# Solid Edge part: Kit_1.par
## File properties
Sűrűség: 0,000 kg/m^3
Pontosság: 0,990
Author: ahadarics
Last saved by: ahadarics
Revision: 79
Username: ahadarics
Dokumentum tartalom típus: 0
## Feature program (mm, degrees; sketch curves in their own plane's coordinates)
base feature "unnamed BaseFeature 1"
thread "unnamed Thread 1"
sketch for "unnamed Hole 1" plane through (0, 0, 93.7) normal (0, 0, 1) x-axis (0, -1, 0)
  hole centre (-16.25, 16.25) bore radius 2.4585
hole "unnamed Hole 1" through
sketch for "unnamed Hole 2" plane through (0, 0, 93.7) normal (0, 0, 1) x-axis (0, -1, 0)
  hole centre (16.25, 16.25) bore radius 2.4585
hole "unnamed Hole 2" through
sketch for "unnamed Hole 3" plane through (0, 0, 93.7) normal (0, 0, 1) x-axis (0, -1, 0)
  hole centre (16.25, -16.25) bore radius 2.4585
hole "unnamed Hole 3" through
sketch for "unnamed Hole 4" plane through (0, 0, 93.7) normal (0, 0, 1) x-axis (0, -1, 0)
  hole centre (-16.25, -16.25) bore radius 2.4585
hole "unnamed Hole 4" through
pattern "unnamed Pattern 1" of "unnamed Hole 1", "unnamed Hole 2", "unnamed Hole 3", "unnamed Hole 4"
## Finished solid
Body 1: solid body, 318 faces, 747 edges, 450 vertices, 4 internal voids.
  Faces by surface: plane 145, cylinder 71, swept 55, torus 25, cone 21, spline 1
  Edges by curve: line 433, circle 187, spline 122, curve on surface 4, intersection 1
Bounding box of the edges (mm; curved faces can reach further): 49.000 x 49.000 x 14.100, from (-24.5, -24.5, 79.6) to (24.5, 24.5, 93.7).
Cylindrical faces by radius (mm): R0.2 x30, R0.335 x1, R0.5307 x1, R1.25 x1, R2.4585 x4, R2.5402 x12, R2.6 x4, R3.75 x4, R4 x4, R4.283 x1, R4.5 x4, R6.27 x1, R6.85 x1, R7 x1, R8.16 x1, R8.25 x1
Conical faces (half-angle, radius in mm at the cone's reference point): 0.5 deg R8 x4, 0.5 deg R8.6 x1, 0.5 deg R10.6 x1, 3 deg R8.205 x1, 7 deg R7.5925 x1, 14 deg R6.135 x1, 14 deg R6.4811 x1, 17 deg R6.135 x1, 23 deg R6.829 x1, 42.5 deg R6.1233 x1, 45 deg R2.8085 x4, 45 deg R7 x1, 84 deg R6.4608 x1, 85 deg R7.9463 x1, 87 deg R6.1765 x1
Toroidal faces (ring radius, tube radius in mm): R2.9402 r0.4 x12, R3.55 r0.2 x8, R6.8057 r0.2025 x1, R7.2522 r0.2925 x1, R7.96 r0.2 x1, R9.0957 r0.5 x1, R10.1043 r0.5 x1
Planar faces by outward normal: +x 11, +y 12, +z 21, -x 9, -y 12, -z 3, oblique 77
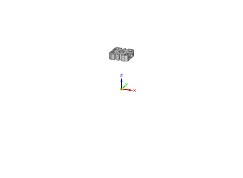
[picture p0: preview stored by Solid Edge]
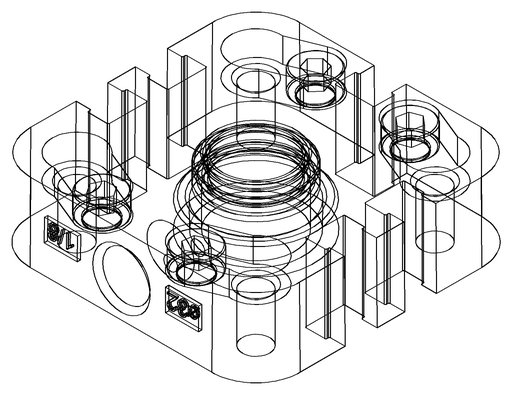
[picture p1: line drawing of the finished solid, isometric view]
